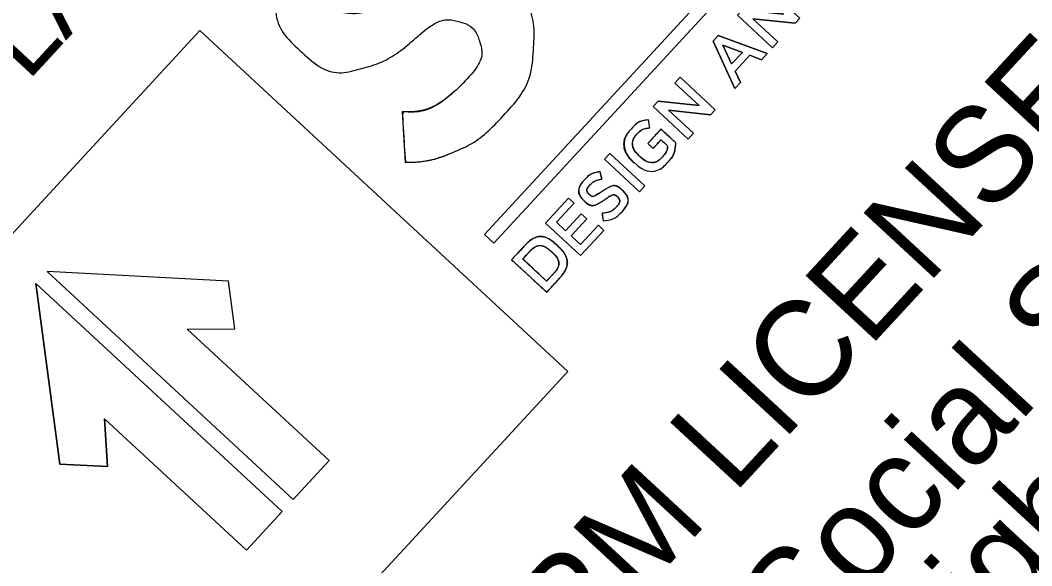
# Model space of a CAD drawing. Extents: x 1768064 to 1770025, y 999327 to 1001342.
# Drawn here: x 1769346.17 to 1769394.23, y 1001025.25 to 1001051.14 of the extents above; entities that cross this region are included whole.
import ezdxf

# ---------------------------------------------------------------- set-up
doc = ezdxf.new("R2010")
doc.units = 0
doc.layers.add('P_NCDOT_Horizontal_Alignment_Station_Major_Label', color=7, linetype='Continuous')

msp = doc.modelspace()

# ---------------------------------------------------------------- linework, layer by layer
at = {"layer": 'P_NCDOT_Horizontal_Alignment_Station_Major_Label'}
for p, q in [((1769364.317, 1001046.802), (1769364.462, 1001044.394)), ((1769376.078, 1001046.03), (1769376.021, 1001046.413)), ((1769375.327, 1001044.386), (1769375.332, 1001044.382)), ((1769375.599, 1001044.681), (1769375.595, 1001044.685)), ((1769373.807, 1001043.597), (1769373.726, 1001043.953)), ((1769373.197, 1001042.874), (1769373.192, 1001042.879)), ((1769374.777, 1001043.07), (1769374.772, 1001043.074)), ((1769372.958, 1001042.574), (1769372.963, 1001042.569)), ((1769374.541, 1001042.767), (1769374.546, 1001042.762)), ((1769373.81, 1001041.981), (1769373.864, 1001041.618)), ((1769371.686, 1001040.447), (1769371.681, 1001040.452)), ((1769371.414, 1001040.153), (1769371.419, 1001040.148))]:
    msp.add_line(p, q, dxfattribs=at)
for points in [[(1769409.949, 1001085.219), (1769368.674, 1001040.566), (1769368.23, 1001040.976), (1769409.506, 1001085.629), (1769409.949, 1001085.219)], [(1769409.506, 1001085.629), (1769368.23, 1001040.976), (1769368.674, 1001040.566), (1769409.949, 1001085.219), (1769409.506, 1001085.629)], [(1769380.246, 1001051.379), (1769380.486, 1001051.64), (1769382.43, 1001051.431), (1769381.278, 1001052.496), (1769381.534, 1001052.773), (1769383.201, 1001051.232), (1769382.983, 1001050.997), (1769380.982, 1001051.211), (1769382.168, 1001050.115), (1769381.913, 1001049.838), (1769380.246, 1001051.379)], [(1769381.913, 1001049.838), (1769382.168, 1001050.115), (1769380.982, 1001051.211), (1769382.983, 1001050.997), (1769383.201, 1001051.232), (1769381.534, 1001052.773), (1769381.278, 1001052.496), (1769382.43, 1001051.431), (1769380.486, 1001051.64), (1769380.246, 1001051.379), (1769381.913, 1001049.838)], [(1769354.695, 1001050.646), (1769336.063, 1001030.489), (1769353.559, 1001014.318), (1769372.191, 1001034.474), (1769354.695, 1001050.646)], [(1769379.09, 1001050.153), (1769379.33, 1001050.413), (1769381.66, 1001049.565), (1769381.385, 1001049.268), (1769380.833, 1001049.478), (1769380.134, 1001048.722), (1769380.384, 1001048.185), (1769380.118, 1001047.897), (1769379.09, 1001050.153)], [(1769380.118, 1001047.897), (1769380.384, 1001048.185), (1769380.134, 1001048.722), (1769380.833, 1001049.478), (1769381.385, 1001049.268), (1769381.66, 1001049.565), (1769379.33, 1001050.413), (1769379.09, 1001050.153), (1769380.118, 1001047.897)], [(1769380.478, 1001049.615), (1769379.556, 1001049.955), (1769379.969, 1001049.064), (1769380.478, 1001049.615)], [(1769379.969, 1001049.064), (1769379.556, 1001049.955), (1769380.478, 1001049.615), (1769379.969, 1001049.064)], [(1769376.235, 1001047.04), (1769376.476, 1001047.301), (1769378.42, 1001047.092), (1769377.267, 1001048.157), (1769377.523, 1001048.434), (1769379.19, 1001046.893), (1769378.972, 1001046.658), (1769376.971, 1001046.872), (1769378.157, 1001045.776), (1769377.902, 1001045.5), (1769376.235, 1001047.04)], [(1769377.902, 1001045.5), (1769378.157, 1001045.776), (1769376.971, 1001046.872), (1769378.972, 1001046.658), (1769379.19, 1001046.893), (1769377.523, 1001048.434), (1769377.267, 1001048.157), (1769378.42, 1001047.092), (1769376.476, 1001047.301), (1769376.235, 1001047.04), (1769377.902, 1001045.5)], [(1769377.312, 1001045.325), (1769376.612, 1001045.972), (1769375.983, 1001045.292), (1769376.238, 1001045.056), (1769376.616, 1001045.465), (1769376.928, 1001045.177)], [(1769373.926, 1001044.542), (1769374.185, 1001044.823), (1769375.852, 1001043.282), (1769375.593, 1001043.001), (1769373.926, 1001044.542)], [(1769375.593, 1001043.001), (1769375.852, 1001043.282), (1769374.185, 1001044.823), (1769373.926, 1001044.542), (1769375.593, 1001043.001)], [(1769371.125, 1001041.512), (1769372.22, 1001042.697), (1769372.482, 1001042.455), (1769371.646, 1001041.551), (1769372.08, 1001041.15), (1769372.821, 1001041.952), (1769373.083, 1001041.71), (1769372.342, 1001040.908), (1769372.789, 1001040.494), (1769373.636, 1001041.41), (1769373.898, 1001041.168), (1769372.792, 1001039.971), (1769371.125, 1001041.512)], [(1769372.792, 1001039.971), (1769373.898, 1001041.168), (1769373.636, 1001041.41), (1769372.789, 1001040.494), (1769372.342, 1001040.908), (1769373.083, 1001041.71), (1769372.821, 1001041.952), (1769372.08, 1001041.15), (1769371.646, 1001041.551), (1769372.482, 1001042.455), (1769372.22, 1001042.697), (1769371.125, 1001041.512), (1769372.792, 1001039.971)], [(1769370.067, 1001040.368), (1769369.516, 1001039.772), (1769371.183, 1001038.231), (1769371.734, 1001038.827)], [(1769371.468, 1001039.074), (1769371.176, 1001038.759), (1769370.043, 1001039.806), (1769370.334, 1001040.122)], [(1769347.441, 1001039.208), (1769359.139, 1001028.395), (1769360.842, 1001030.238), (1769354.095, 1001036.475), (1769356.358, 1001036.499), (1769356.068, 1001038.757), (1769347.441, 1001039.208)], [(1769346.917, 1001038.641), (1769358.615, 1001027.828), (1769356.911, 1001025.985), (1769350.164, 1001032.222), (1769350.317, 1001029.964), (1769348.043, 1001030.076), (1769346.917, 1001038.641)], [(1769348.043, 1001030.076), (1769350.317, 1001029.964), (1769350.164, 1001032.222), (1769356.911, 1001025.985), (1769358.615, 1001027.828), (1769346.917, 1001038.641), (1769348.043, 1001030.076)]]:
    msp.add_lwpolyline(points, dxfattribs=at)
for points in [[(1769336.063, 1001030.489), (1769354.695, 1001050.646), (1769372.191, 1001034.474), (1769353.559, 1001014.318)], [(1769347.441, 1001039.208), (1769359.139, 1001028.395), (1769360.842, 1001030.238), (1769354.095, 1001036.475), (1769356.358, 1001036.499), (1769356.068, 1001038.757)]]:
    msp.add_lwpolyline(points, close=True, dxfattribs=at)
for points, degree in [([(1769361.728, 1001057.209), (1769362.375, 1001057.483), (1769363.101, 1001057.627), (1769363.905, 1001057.641), (1769363.905, 1001057.641), (1769364.05, 1001055.234), (1769364.05, 1001055.234), (1769363.161, 1001055.297), (1769362.376, 1001054.962), (1769361.696, 1001054.226), (1769361.016, 1001053.49), (1769360.763, 1001052.853), (1769360.936, 1001052.313), (1769361.11, 1001051.774), (1769361.418, 1001051.489), (1769361.863, 1001051.457), (1769362.308, 1001051.425), (1769362.934, 1001051.718), (1769363.741, 1001052.335), (1769364.544, 1001053.033), (1769365.463, 1001053.492), (1769366.496, 1001053.712), (1769367.529, 1001053.932), (1769368.535, 1001053.589), (1769369.515, 1001052.682), (1769370.283, 1001051.973), (1769370.631, 1001051.025), (1769370.559, 1001049.837), (1769370.488, 1001048.648), (1769370.037, 1001047.604), (1769369.205, 1001046.704), (1769368.416, 1001045.85), (1769367.629, 1001045.255), (1769366.844, 1001044.919), (1769366.059, 1001044.584), (1769365.265, 1001044.409), (1769364.462, 1001044.394), (1769364.462, 1001044.394), (1769364.317, 1001046.802), (1769364.317, 1001046.802), (1769365.206, 1001046.738), (1769366.146, 1001047.157), (1769367.138, 1001048.059), (1769367.894, 1001048.877), (1769368.184, 1001049.554), (1769368.009, 1001050.091), (1769367.834, 1001050.628), (1769367.471, 1001050.963), (1769366.922, 1001051.096), (1769366.373, 1001051.228), (1769365.678, 1001050.924), (1769364.837, 1001050.186), (1769364.072, 1001049.529), (1769363.214, 1001049.071), (1769362.263, 1001048.813), (1769361.313, 1001048.554), (1769360.369, 1001048.858), (1769359.432, 1001049.724), (1769358.584, 1001050.508), (1769358.226, 1001051.486), (1769358.356, 1001052.658), (1769358.486, 1001053.83), (1769358.892, 1001054.783), (1769359.572, 1001055.518), (1769360.362, 1001056.373), (1769361.08, 1001056.937), (1769361.728, 1001057.209)], 3), ([(1769361.728, 1001057.209), (1769361.08, 1001056.937), (1769360.362, 1001056.373), (1769359.572, 1001055.518), (1769358.892, 1001054.783), (1769358.486, 1001053.83), (1769358.356, 1001052.658), (1769358.226, 1001051.486), (1769358.584, 1001050.508), (1769359.432, 1001049.724), (1769360.369, 1001048.858), (1769361.313, 1001048.554), (1769362.263, 1001048.813), (1769363.214, 1001049.071), (1769364.072, 1001049.529), (1769364.837, 1001050.186), (1769365.678, 1001050.924), (1769366.373, 1001051.228), (1769366.922, 1001051.096), (1769367.471, 1001050.963), (1769367.834, 1001050.628), (1769368.009, 1001050.091), (1769368.184, 1001049.554), (1769367.894, 1001048.877), (1769367.138, 1001048.059), (1769366.146, 1001047.157), (1769365.206, 1001046.738), (1769364.317, 1001046.802)], 3), ([(1769364.462, 1001044.394), (1769365.265, 1001044.409), (1769366.059, 1001044.584), (1769366.844, 1001044.919), (1769367.629, 1001045.255), (1769368.416, 1001045.85), (1769369.205, 1001046.704), (1769370.037, 1001047.604), (1769370.488, 1001048.648), (1769370.559, 1001049.837), (1769370.631, 1001051.025), (1769370.283, 1001051.973), (1769369.515, 1001052.682), (1769368.535, 1001053.589), (1769367.529, 1001053.932), (1769366.496, 1001053.712), (1769365.463, 1001053.492), (1769364.544, 1001053.033), (1769363.741, 1001052.335), (1769362.934, 1001051.718), (1769362.308, 1001051.425), (1769361.863, 1001051.457), (1769361.418, 1001051.489), (1769361.11, 1001051.774), (1769360.936, 1001052.313), (1769360.763, 1001052.853), (1769361.016, 1001053.49), (1769361.696, 1001054.226), (1769362.376, 1001054.962), (1769363.161, 1001055.297), (1769364.05, 1001055.234)], 3), ([(1769375.332, 1001044.382), (1769375.332, 1001044.382), (1769375.327, 1001044.386), (1769375.327, 1001044.386), (1769374.86, 1001044.818), (1769374.781, 1001045.525), (1769375.227, 1001046.007), (1769375.485, 1001046.286), (1769375.724, 1001046.383), (1769376.021, 1001046.413), (1769376.021, 1001046.413), (1769376.078, 1001046.03), (1769376.078, 1001046.03), (1769375.854, 1001046.008), (1769375.674, 1001045.951), (1769375.486, 1001045.747), (1769375.213, 1001045.453), (1769375.275, 1001044.98), (1769375.595, 1001044.685), (1769375.595, 1001044.685), (1769375.599, 1001044.681), (1769375.599, 1001044.681), (1769375.942, 1001044.364), (1769376.395, 1001044.347), (1769376.697, 1001044.674), (1769376.836, 1001044.825), (1769376.913, 1001045.008), (1769376.928, 1001045.177), (1769376.928, 1001045.177), (1769376.616, 1001045.465), (1769376.616, 1001045.465), (1769376.616, 1001045.465), (1769376.238, 1001045.056), (1769376.238, 1001045.056), (1769376.238, 1001045.056), (1769375.983, 1001045.292), (1769375.983, 1001045.292), (1769375.983, 1001045.292), (1769376.612, 1001045.972), (1769376.612, 1001045.972), (1769376.612, 1001045.972), (1769377.312, 1001045.325), (1769377.312, 1001045.325), (1769377.307, 1001045.038), (1769377.217, 1001044.701), (1769376.956, 1001044.418), (1769376.493, 1001043.918), (1769375.818, 1001043.933), (1769375.332, 1001044.382)], 3), ([(1769376.021, 1001046.413), (1769375.724, 1001046.383), (1769375.485, 1001046.286), (1769375.227, 1001046.007), (1769374.781, 1001045.525), (1769374.86, 1001044.818), (1769375.327, 1001044.386)], 3), ([(1769375.595, 1001044.685), (1769375.275, 1001044.98), (1769375.213, 1001045.453), (1769375.486, 1001045.747), (1769375.674, 1001045.951), (1769375.854, 1001046.008), (1769376.078, 1001046.03)], 3), ([(1769375.332, 1001044.382), (1769375.818, 1001043.933), (1769376.493, 1001043.918), (1769376.956, 1001044.418), (1769377.217, 1001044.701), (1769377.307, 1001045.038), (1769377.312, 1001045.325)], 3), ([(1769376.928, 1001045.177), (1769376.913, 1001045.008), (1769376.836, 1001044.825), (1769376.697, 1001044.674), (1769376.395, 1001044.347), (1769375.942, 1001044.364), (1769375.599, 1001044.681)], 3), ([(1769373.726, 1001043.953), (1769373.44, 1001043.916), (1769373.195, 1001043.799), (1769372.98, 1001043.566), (1769372.686, 1001043.249), (1769372.673, 1001042.838), (1769372.958, 1001042.574)], 3), ([(1769373.864, 1001041.618), (1769373.864, 1001041.618), (1769373.81, 1001041.981), (1769373.81, 1001041.981), (1769374.09, 1001042.006), (1769374.312, 1001042.089), (1769374.494, 1001042.286), (1769374.654, 1001042.459), (1769374.67, 1001042.648), (1769374.546, 1001042.762), (1769374.546, 1001042.762), (1769374.541, 1001042.767), (1769374.541, 1001042.767), (1769374.422, 1001042.877), (1769374.299, 1001042.872), (1769373.953, 1001042.641), (1769373.553, 1001042.38), (1769373.27, 1001042.285), (1769372.963, 1001042.569), (1769372.963, 1001042.569), (1769372.958, 1001042.574), (1769372.958, 1001042.574), (1769372.673, 1001042.838), (1769372.686, 1001043.249), (1769372.98, 1001043.566), (1769373.195, 1001043.799), (1769373.44, 1001043.916), (1769373.726, 1001043.953), (1769373.726, 1001043.953), (1769373.807, 1001043.597), (1769373.807, 1001043.597), (1769373.563, 1001043.557), (1769373.37, 1001043.468), (1769373.235, 1001043.322), (1769373.083, 1001043.158), (1769373.082, 1001042.98), (1769373.192, 1001042.879), (1769373.192, 1001042.879), (1769373.197, 1001042.874), (1769373.197, 1001042.874), (1769373.325, 1001042.755), (1769373.45, 1001042.776), (1769373.811, 1001043.014), (1769374.209, 1001043.272), (1769374.496, 1001043.329), (1769374.772, 1001043.074), (1769374.772, 1001043.074), (1769374.777, 1001043.07), (1769374.777, 1001043.07), (1769375.089, 1001042.781), (1769375.057, 1001042.374), (1769374.747, 1001042.039), (1769374.521, 1001041.794), (1769374.22, 1001041.645), (1769373.864, 1001041.618)], 3), ([(1769373.192, 1001042.879), (1769373.082, 1001042.98), (1769373.083, 1001043.158), (1769373.235, 1001043.322), (1769373.37, 1001043.468), (1769373.563, 1001043.557), (1769373.807, 1001043.597)], 3), ([(1769374.772, 1001043.074), (1769374.496, 1001043.329), (1769374.209, 1001043.272), (1769373.811, 1001043.014), (1769373.45, 1001042.776), (1769373.325, 1001042.755), (1769373.197, 1001042.874)], 3), ([(1769372.963, 1001042.569), (1769373.27, 1001042.285), (1769373.553, 1001042.38), (1769373.953, 1001042.641), (1769374.299, 1001042.872), (1769374.422, 1001042.877), (1769374.541, 1001042.767)], 3), ([(1769373.864, 1001041.618), (1769374.22, 1001041.645), (1769374.521, 1001041.794), (1769374.747, 1001042.039), (1769375.057, 1001042.374), (1769375.089, 1001042.781), (1769374.777, 1001043.07)], 3), ([(1769374.546, 1001042.762), (1769374.67, 1001042.648), (1769374.654, 1001042.459), (1769374.494, 1001042.286), (1769374.312, 1001042.089), (1769374.09, 1001042.006), (1769373.81, 1001041.981)], 3), ([(1769369.516, 1001039.772), (1769369.516, 1001039.772), (1769370.067, 1001040.368), (1769370.067, 1001040.368), (1769370.532, 1001040.871), (1769371.212, 1001040.885), (1769371.681, 1001040.452), (1769371.681, 1001040.452), (1769371.686, 1001040.447), (1769371.686, 1001040.447), (1769372.155, 1001040.014), (1769372.199, 1001039.33), (1769371.734, 1001038.827), (1769371.734, 1001038.827), (1769371.183, 1001038.231), (1769371.183, 1001038.231), (1769371.183, 1001038.231), (1769369.516, 1001039.772), (1769369.516, 1001039.772)], 3), ([(1769371.681, 1001040.452), (1769371.212, 1001040.885), (1769370.532, 1001040.871), (1769370.067, 1001040.368)], 2), ([(1769370.043, 1001039.806), (1769370.043, 1001039.806), (1769371.176, 1001038.759), (1769371.176, 1001038.759), (1769371.176, 1001038.759), (1769371.468, 1001039.074), (1769371.468, 1001039.074), (1769371.778, 1001039.409), (1769371.745, 1001039.847), (1769371.419, 1001040.148), (1769371.419, 1001040.148), (1769371.414, 1001040.153), (1769371.414, 1001040.153), (1769371.088, 1001040.454), (1769370.644, 1001040.457), (1769370.334, 1001040.122), (1769370.334, 1001040.122), (1769370.043, 1001039.806), (1769370.043, 1001039.806)], 3), ([(1769370.334, 1001040.122), (1769370.644, 1001040.457), (1769371.088, 1001040.454), (1769371.414, 1001040.153)], 2), ([(1769371.734, 1001038.827), (1769372.199, 1001039.33), (1769372.155, 1001040.014), (1769371.686, 1001040.447)], 2), ([(1769371.419, 1001040.148), (1769371.745, 1001039.847), (1769371.778, 1001039.409), (1769371.468, 1001039.074)], 2)]:
    msp.add_open_spline(points, degree=degree, dxfattribs=at)

# ---------------------------------------------------------------- texts
for s, height, p in [('DOCUMENT NOT CONSIDERED FINAL', 3.59815, (1769323.012, 1001042.99)), ('UNLESS ALL SIGNATURES COMPLETED', 3.59815, (1769324.782, 1001038.045)), ('PLANS PREPARED BY:', 3.59788, (1769344.337, 1001045.843)), ('NC FIRM LICENSE No: C-5176', 4.55564, (1769361.678, 1001008.716)), ('1000 Social St. Suite 800.', 4.55564, (1769372.975, 1001009.653)), ('Raleigh, NC 27609', 4.55564, (1769383.831, 1001012.68)), ('(919) 732-6676 (FAX)', 4.55564, (1769389.866, 1001001.773)), ('(919) 732-3883', 4.55564, (1769391.662, 1001012.433))]:
    msp.add_text(s, height=height, rotation=47.2512, dxfattribs=at).set_placement(p)

doc.saveas('drawing.dxf')
